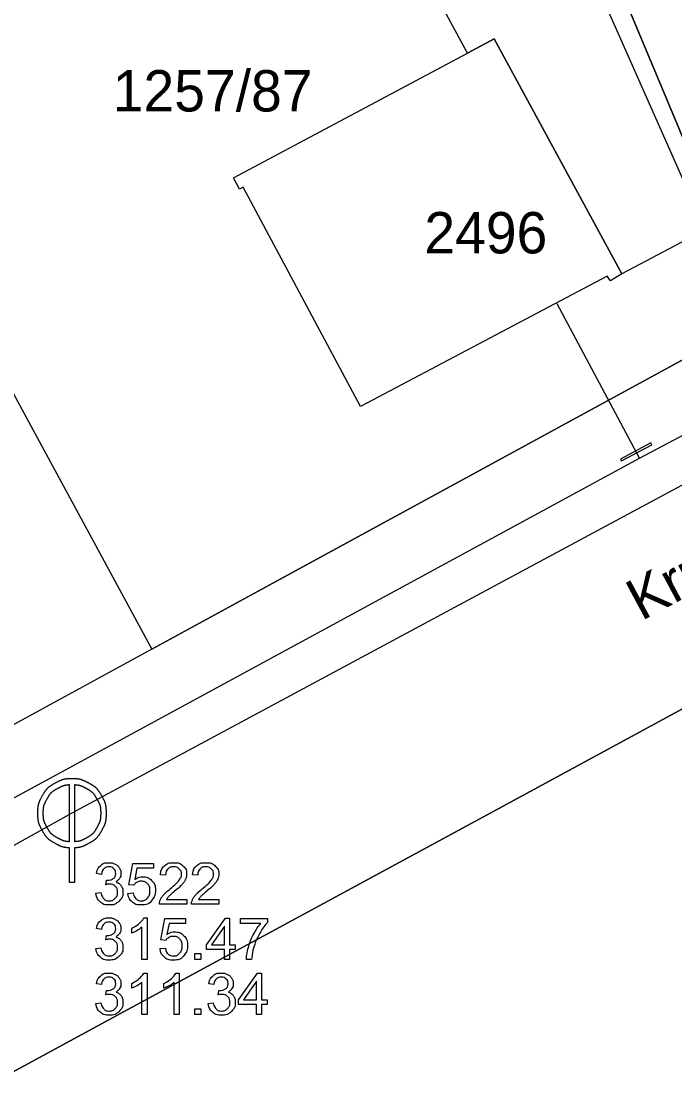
# Model space of a CAD drawing. Extents: x -562248 to -562040, y -1079385 to -1079027.
# Drawn here: x -562140.7 to -562116.99, y -1079306.51 to -1079267.68 of the extents above; entities that cross this region are included whole.
import ezdxf

# ---------------------------------------------------------------- set-up
doc = ezdxf.new("R2010")
doc.units = 0
for name, color, linetype in [('Armatura vodovodní', 7, 'Continuous'), ('Default', 7, 'Continuous'), ('Kanalizační stoka', 7, 'Continuous'), ('Kanalizační šachta', 7, 'Continuous'), ('Parcela-polygon', 7, 'Continuous'), ('Parcela-text', 7, 'Continuous'), ('Popis kmenové stoky', 7, 'Continuous'), ('Popis šachty', 7, 'Continuous'), ('Vodovodní přípojka', 7, 'Continuous'), ('Vodovodní řad', 7, 'Continuous')]:
    doc.layers.add(name, color=color, linetype=linetype)

msp = doc.modelspace()

# ---------------------------------------------------------------- linework, layer by layer
at = {"layer": 'Armatura vodovodní'}
msp.add_lwpolyline([(-562118.912, -1079283.63), (-562117.81, -1079283.04), (-562117.847, -1079282.971), (-562118.949, -1079283.561)], close=True, dxfattribs=at)
at = {"layer": 'Default'}
for points in [[(-562139.475, -1079295.321), (-562139.674, -1079295.429), (-562139.829, -1079295.582), (-562139.942, -1079295.783)], [(-562139.763, -1079295.889), (-562139.671, -1079295.722), (-562139.541, -1079295.594), (-562139.375, -1079295.504)], [(-562138.86, -1079295.16), (-562139.072, -1079295.16), (-562139.277, -1079295.214), (-562139.475, -1079295.321)], [(-562139.375, -1079295.504), (-562139.232, -1079295.428), (-562139.094, -1079295.384), (-562138.963, -1079295.372)], [(-562138.246, -1079295.321), (-562138.445, -1079295.214), (-562138.65, -1079295.16), (-562138.86, -1079295.16)], [(-562138.757, -1079295.372), (-562138.626, -1079295.384), (-562138.489, -1079295.428), (-562138.347, -1079295.504)], [(-562138.347, -1079295.504), (-562138.181, -1079295.594), (-562138.051, -1079295.722), (-562137.958, -1079295.889)], [(-562137.778, -1079295.783), (-562137.891, -1079295.582), (-562138.047, -1079295.429), (-562138.246, -1079295.321)], [(-562139.942, -1079295.783), (-562140.054, -1079295.983), (-562140.11, -1079296.192), (-562140.11, -1079296.41)], [(-562139.902, -1079296.41), (-562139.902, -1079296.229), (-562139.856, -1079296.056), (-562139.763, -1079295.889)], [(-562137.958, -1079295.889), (-562137.864, -1079296.056), (-562137.818, -1079296.229), (-562137.818, -1079296.41)], [(-562137.61, -1079296.41), (-562137.61, -1079296.192), (-562137.666, -1079295.983), (-562137.778, -1079295.783)], [(-562140.11, -1079296.41), (-562140.11, -1079296.626), (-562140.055, -1079296.834), (-562139.945, -1079297.033)], [(-562139.766, -1079296.928), (-562139.857, -1079296.763), (-562139.902, -1079296.591), (-562139.902, -1079296.41)], [(-562137.818, -1079296.41), (-562137.818, -1079296.591), (-562137.863, -1079296.763), (-562137.954, -1079296.928)], [(-562137.775, -1079297.033), (-562137.665, -1079296.834), (-562137.61, -1079296.626), (-562137.61, -1079296.41)], [(-562139.945, -1079297.033), (-562139.835, -1079297.231), (-562139.681, -1079297.385), (-562139.483, -1079297.494)], [(-562139.38, -1079297.311), (-562139.546, -1079297.22), (-562139.675, -1079297.092), (-562139.766, -1079296.928)], [(-562137.954, -1079296.928), (-562138.045, -1079297.092), (-562138.173, -1079297.22), (-562138.338, -1079297.311)], [(-562138.237, -1079297.494), (-562138.039, -1079297.385), (-562137.885, -1079297.231), (-562137.775, -1079297.033)], [(-562138.963, -1079297.445), (-562139.099, -1079297.435), (-562139.238, -1079297.391), (-562139.38, -1079297.311)], [(-562138.338, -1079297.311), (-562138.481, -1079297.391), (-562138.621, -1079297.435), (-562138.757, -1079297.445)], [(-562139.483, -1079297.494), (-562139.308, -1079297.592), (-562139.135, -1079297.646), (-562138.963, -1079297.658)], [(-562138.757, -1079297.658), (-562138.585, -1079297.646), (-562138.412, -1079297.592), (-562138.237, -1079297.494)]]:
    msp.add_open_spline(points, degree=2, dxfattribs=at)
at = {"layer": 'Kanalizační stoka'}
for points in [[(-562077.25, -1079263.3), (-562101.861, -1079276.526), (-562138.86, -1079296.41)], [(-562138.86, -1079296.41), (-562202.88, -1079332.07)]]:
    msp.add_lwpolyline(points, dxfattribs=at)
at = {"layer": 'Kanalizační šachta'}
for points in [[(-562138.963, -1079295.372), (-562138.963, -1079297.445)], [(-562138.757, -1079297.445), (-562138.757, -1079295.372)], [(-562138.963, -1079298.91), (-562138.757, -1079298.91), (-562138.757, -1079297.658)], [(-562138.963, -1079297.658), (-562138.963, -1079298.91)]]:
    msp.add_lwpolyline(points, dxfattribs=at)
at = {"layer": 'Parcela-polygon'}
for points in [[(-562125.839, -1079250.062), (-562115.46, -1079274.84), (-562111.34, -1079272.6), (-562115.82, -1079264.13), (-562111.86, -1079261.96), (-562112.48, -1079260.84), (-562109.81, -1079259.38), (-562109.2, -1079260.5), (-562101.14, -1079256.08), (-562102.73, -1079253.17), (-562100.18, -1079251.98), (-562102.28, -1079247.51), (-562108.03, -1079234.16), (-562113.76, -1079220.84), (-562114.87, -1079218.31), (-562116.77, -1079219.12), (-562123.59, -1079221.97), (-562126.807, -1079223.131)], [(-562050.734, -1079242.89), (-562074.7, -1079253.09), (-562082.29, -1079260.79), (-562083.07, -1079261.58), (-562094.62, -1079267.87), (-562113.94, -1079278.46), (-562131.57, -1079288.07), (-562135.96, -1079290.46), (-562143.99, -1079294.84), (-562166.66, -1079307.21), (-562184.27, -1079316.57), (-562201.76, -1079326), (-562209.06, -1079330.03), (-562233.192, -1079343.166)], [(-562150.955, -1079262.816), (-562144.68, -1079274.39), (-562135.96, -1079290.46), (-562131.57, -1079288.07), (-562113.94, -1079278.46), (-562115.46, -1079274.84), (-562125.839, -1079250.062)], [(-562128.35, -1079262.95), (-562129.18, -1079261.41), (-562128.95, -1079260.62), (-562129.48, -1079259.64), (-562133.24, -1079261.69), (-562134.9, -1079261.17), (-562136.63, -1079257.94), (-562126.97, -1079252.69), (-562121.01, -1079263.69), (-562121.23, -1079263.8), (-562119.71, -1079266.58), (-562115.88, -1079275.25), (-562118.9, -1079276.84), (-562119.32, -1079277.09), (-562119.43, -1079276.92), (-562128.39, -1079281.65), (-562132.65, -1079273.7), (-562132.78, -1079273.77), (-562133, -1079273.36), (-562124.5, -1079268.83), (-562127.56, -1079263.19), (-562128.35, -1079262.95)], [(-562231.237, -1079347.297), (-562217.17, -1079339.57), (-562199.49, -1079329.98), (-562196.37, -1079335.83), (-562192.03, -1079333.48), (-562171.25, -1079322.22), (-562167.46, -1079320.16), (-562158.91, -1079315.52), (-562136.96, -1079303.61), (-562123.37, -1079296.24), (-562109.61, -1079288.78), (-562108.06, -1079292.36), (-562077.04, -1079275.54), (-562045.434, -1079258.412)], [(-562098.09, -1079312.42), (-562108.06, -1079292.36), (-562109.61, -1079288.78), (-562123.37, -1079296.24), (-562136.96, -1079303.61), (-562158.91, -1079315.52), (-562167.46, -1079320.16), (-562171.25, -1079322.22), (-562162.29, -1079338.64), (-562157.03, -1079335.76), (-562146.49, -1079329.95), (-562141.95, -1079327.52), (-562136.58, -1079324.65), (-562135.92, -1079324.29), (-562132.83, -1079322.64), (-562130.32, -1079321.29), (-562116.03, -1079313.64), (-562103.22, -1079306.78), (-562099.68, -1079313.416)]]:
    msp.add_lwpolyline(points, dxfattribs=at)
for points in [[(-562129.18, -1079261.41), (-562128.95, -1079260.62), (-562129.48, -1079259.64), (-562133.24, -1079261.69), (-562134.9, -1079261.17), (-562136.63, -1079257.94), (-562126.97, -1079252.69), (-562121.01, -1079263.69), (-562121.23, -1079263.8), (-562119.71, -1079266.58), (-562115.88, -1079275.25), (-562118.9, -1079276.84), (-562123.54, -1079268.32), (-562124.5, -1079268.83), (-562127.56, -1079263.19), (-562128.35, -1079262.95)], [(-562133, -1079273.36), (-562124.5, -1079268.83), (-562123.54, -1079268.32), (-562118.9, -1079276.84), (-562119.32, -1079277.09), (-562119.43, -1079276.92), (-562128.39, -1079281.65), (-562132.65, -1079273.7), (-562132.78, -1079273.77)], [(-562144.68, -1079274.39), (-562135.96, -1079290.46), (-562143.99, -1079294.84), (-562145.99, -1079291.34), (-562153.85, -1079295.62), (-562159, -1079286.21), (-562160.69, -1079283.12), (-562153.22, -1079278.89), (-562145.79, -1079274.97)]]:
    msp.add_lwpolyline(points, close=True, dxfattribs=at)
at = {"layer": 'Popis šachty'}
for points in [[(-562136.622, -1079299.027), (-562136.795, -1079299.004), (-562136.65, -1079298.233), (-562135.904, -1079298.233), (-562135.904, -1079298.41), (-562136.503, -1079298.41), (-562136.583, -1079298.812)], [(-562137.79, -1079298.63), (-562137.974, -1079298.597)], [(-562135.463, -1079298.661), (-562135.653, -1079298.642)], [(-562134.298, -1079298.661), (-562134.488, -1079298.642)], [(-562137.629, -1079299.003), (-562137.608, -1079298.842)], [(-562137.992, -1079299.316), (-562137.808, -1079299.292)], [(-562136.828, -1079299.321), (-562136.635, -1079299.305)], [(-562134.696, -1079299.537), (-562134.696, -1079299.714), (-562135.687, -1079299.714)], [(-562135.431, -1079299.537), (-562134.696, -1079299.537)], [(-562133.531, -1079299.537), (-562133.531, -1079299.714), (-562134.522, -1079299.714)], [(-562134.266, -1079299.537), (-562133.531, -1079299.537)], [(-562136.687, -1079300.763), (-562136.687, -1079300.585)], [(-562136.135, -1079301.714), (-562136.319, -1079301.714), (-562136.319, -1079300.541)], [(-562136.254, -1079300.208), (-562136.135, -1079300.208), (-562136.135, -1079301.714)], [(-562135.457, -1079301.027), (-562135.63, -1079301.004), (-562135.485, -1079300.233), (-562134.739, -1079300.233), (-562134.739, -1079300.41), (-562135.338, -1079300.41), (-562135.418, -1079300.812)], [(-562133.326, -1079301.714), (-562133.326, -1079301.355), (-562133.977, -1079301.355), (-562133.977, -1079301.186), (-562133.293, -1079300.214), (-562133.142, -1079300.214), (-562133.142, -1079301.186), (-562132.94, -1079301.186), (-562132.94, -1079301.355), (-562133.142, -1079301.355), (-562133.142, -1079301.714), (-562133.326, -1079301.714)], [(-562133.326, -1079301.186), (-562133.326, -1079300.509), (-562133.796, -1079301.186), (-562133.326, -1079301.186)], [(-562132.739, -1079300.411), (-562132.739, -1079300.233), (-562131.768, -1079300.233), (-562131.768, -1079300.377)], [(-562132.005, -1079300.411), (-562132.739, -1079300.411)], [(-562137.79, -1079300.63), (-562137.974, -1079300.597)], [(-562137.629, -1079301.003), (-562137.608, -1079300.842)], [(-562137.992, -1079301.316), (-562137.808, -1079301.292)], [(-562135.663, -1079301.321), (-562135.47, -1079301.305)], [(-562134.395, -1079301.714), (-562134.395, -1079301.505), (-562134.186, -1079301.505), (-562134.186, -1079301.714), (-562134.395, -1079301.714)], [(-562132.34, -1079301.714), (-562132.529, -1079301.714)], [(-562136.254, -1079302.208), (-562136.135, -1079302.208), (-562136.135, -1079303.714)], [(-562135.089, -1079302.208), (-562134.97, -1079302.208), (-562134.97, -1079303.714)], [(-562132.161, -1079303.714), (-562132.161, -1079303.355), (-562132.812, -1079303.355), (-562132.812, -1079303.186), (-562132.128, -1079302.214), (-562131.977, -1079302.214), (-562131.977, -1079303.186), (-562131.775, -1079303.186), (-562131.775, -1079303.355), (-562131.977, -1079303.355), (-562131.977, -1079303.714), (-562132.161, -1079303.714)], [(-562132.161, -1079303.186), (-562132.161, -1079302.509), (-562132.631, -1079303.186), (-562132.161, -1079303.186)], [(-562137.79, -1079302.63), (-562137.974, -1079302.597)], [(-562137.629, -1079303.003), (-562137.608, -1079302.842)], [(-562136.687, -1079302.763), (-562136.687, -1079302.585)], [(-562136.135, -1079303.714), (-562136.319, -1079303.714), (-562136.319, -1079302.541)], [(-562135.522, -1079302.763), (-562135.522, -1079302.585)], [(-562134.97, -1079303.714), (-562135.154, -1079303.714), (-562135.154, -1079302.541)], [(-562133.713, -1079302.63), (-562133.897, -1079302.597)], [(-562133.552, -1079303.003), (-562133.531, -1079302.842)], [(-562137.992, -1079303.316), (-562137.808, -1079303.292)], [(-562133.915, -1079303.316), (-562133.731, -1079303.292)], [(-562134.395, -1079303.714), (-562134.395, -1079303.505), (-562134.186, -1079303.505), (-562134.186, -1079303.714), (-562134.395, -1079303.714)]]:
    msp.add_lwpolyline(points, dxfattribs=at)
for points in [[(-562137.974, -1079298.597), (-562137.94, -1079298.412), (-562137.82, -1079298.31), (-562137.7, -1079298.208), (-562137.522, -1079298.208), (-562137.399, -1079298.208), (-562137.296, -1079298.261), (-562137.193, -1079298.314), (-562137.138, -1079298.404), (-562137.083, -1079298.495), (-562137.083, -1079298.597), (-562137.083, -1079298.695), (-562137.135, -1079298.774), (-562137.187, -1079298.854), (-562137.29, -1079298.901), (-562137.157, -1079298.932), (-562137.083, -1079299.028), (-562137.01, -1079299.125), (-562137.01, -1079299.27), (-562137.01, -1079299.466), (-562137.153, -1079299.603), (-562137.296, -1079299.739), (-562137.515, -1079299.739), (-562137.713, -1079299.739), (-562137.843, -1079299.621), (-562137.974, -1079299.504), (-562137.992, -1079299.316)], [(-562135.653, -1079298.642), (-562135.633, -1079298.43), (-562135.506, -1079298.319), (-562135.38, -1079298.208), (-562135.166, -1079298.208), (-562134.95, -1079298.208), (-562134.824, -1079298.328), (-562134.698, -1079298.448), (-562134.698, -1079298.624), (-562134.698, -1079298.714), (-562134.735, -1079298.801), (-562134.772, -1079298.888), (-562134.857, -1079298.984), (-562134.942, -1079299.081), (-562135.141, -1079299.248), (-562135.306, -1079299.387), (-562135.353, -1079299.437), (-562135.4, -1079299.487), (-562135.431, -1079299.537)], [(-562134.488, -1079298.642), (-562134.468, -1079298.43), (-562134.341, -1079298.319), (-562134.215, -1079298.208), (-562134.001, -1079298.208), (-562133.785, -1079298.208), (-562133.659, -1079298.328), (-562133.533, -1079298.448), (-562133.533, -1079298.624), (-562133.533, -1079298.714), (-562133.57, -1079298.801), (-562133.607, -1079298.888), (-562133.692, -1079298.984), (-562133.777, -1079299.081), (-562133.976, -1079299.248), (-562134.141, -1079299.387), (-562134.188, -1079299.437), (-562134.235, -1079299.487), (-562134.266, -1079299.537)], [(-562137.608, -1079298.842), (-562137.59, -1079298.844), (-562137.579, -1079298.844), (-562137.461, -1079298.844), (-562137.367, -1079298.782), (-562137.273, -1079298.721), (-562137.273, -1079298.593), (-562137.273, -1079298.492), (-562137.341, -1079298.426), (-562137.41, -1079298.359), (-562137.518, -1079298.359), (-562137.626, -1079298.359), (-562137.698, -1079298.427), (-562137.769, -1079298.495), (-562137.79, -1079298.63)], [(-562135.687, -1079299.714), (-562135.689, -1079299.647), (-562135.666, -1079299.586), (-562135.628, -1079299.485), (-562135.544, -1079299.386), (-562135.461, -1079299.288), (-562135.303, -1079299.16), (-562135.059, -1079298.959), (-562134.974, -1079298.842), (-562134.888, -1079298.725), (-562134.888, -1079298.62), (-562134.888, -1079298.511), (-562134.966, -1079298.435), (-562135.044, -1079298.36), (-562135.17, -1079298.36), (-562135.303, -1079298.36), (-562135.382, -1079298.44), (-562135.462, -1079298.52), (-562135.463, -1079298.661)], [(-562134.522, -1079299.714), (-562134.524, -1079299.647), (-562134.501, -1079299.586), (-562134.463, -1079299.485), (-562134.379, -1079299.386), (-562134.296, -1079299.288), (-562134.138, -1079299.16), (-562133.894, -1079298.959), (-562133.809, -1079298.842), (-562133.723, -1079298.725), (-562133.723, -1079298.62), (-562133.723, -1079298.511), (-562133.801, -1079298.435), (-562133.879, -1079298.36), (-562134.005, -1079298.36), (-562134.138, -1079298.36), (-562134.217, -1079298.44), (-562134.297, -1079298.52), (-562134.298, -1079298.661)], [(-562137.808, -1079299.292), (-562137.776, -1079299.449), (-562137.7, -1079299.518), (-562137.624, -1079299.587), (-562137.514, -1079299.587), (-562137.384, -1079299.587), (-562137.295, -1079299.497), (-562137.205, -1079299.407), (-562137.205, -1079299.274), (-562137.205, -1079299.147), (-562137.288, -1079299.065), (-562137.371, -1079298.982), (-562137.499, -1079298.982), (-562137.551, -1079298.982), (-562137.629, -1079299.003)], [(-562136.583, -1079298.812), (-562136.448, -1079298.718), (-562136.3, -1079298.718), (-562136.104, -1079298.718), (-562135.968, -1079298.854), (-562135.833, -1079298.991), (-562135.833, -1079299.205), (-562135.833, -1079299.408), (-562135.952, -1079299.557), (-562136.096, -1079299.739), (-562136.346, -1079299.739), (-562136.551, -1079299.739), (-562136.68, -1079299.625), (-562136.81, -1079299.51), (-562136.828, -1079299.321)], [(-562136.635, -1079299.305), (-562136.613, -1079299.446), (-562136.535, -1079299.517), (-562136.457, -1079299.588), (-562136.346, -1079299.588), (-562136.212, -1079299.588), (-562136.121, -1079299.488), (-562136.029, -1079299.387), (-562136.029, -1079299.221), (-562136.029, -1079299.063), (-562136.117, -1079298.972), (-562136.205, -1079298.881), (-562136.349, -1079298.881), (-562136.439, -1079298.881), (-562136.51, -1079298.921), (-562136.581, -1079298.962), (-562136.622, -1079299.027)], [(-562137.974, -1079300.597), (-562137.94, -1079300.412), (-562137.82, -1079300.31), (-562137.7, -1079300.208), (-562137.522, -1079300.208), (-562137.399, -1079300.208), (-562137.296, -1079300.261), (-562137.193, -1079300.314), (-562137.138, -1079300.404), (-562137.083, -1079300.495), (-562137.083, -1079300.597), (-562137.083, -1079300.695), (-562137.135, -1079300.774), (-562137.187, -1079300.854), (-562137.29, -1079300.901), (-562137.157, -1079300.932), (-562137.083, -1079301.028), (-562137.01, -1079301.125), (-562137.01, -1079301.27), (-562137.01, -1079301.466), (-562137.153, -1079301.603), (-562137.296, -1079301.739), (-562137.515, -1079301.739), (-562137.713, -1079301.739), (-562137.843, -1079301.621), (-562137.974, -1079301.504), (-562137.992, -1079301.316)], [(-562137.608, -1079300.842), (-562137.59, -1079300.844), (-562137.579, -1079300.844), (-562137.461, -1079300.844), (-562137.367, -1079300.782), (-562137.273, -1079300.721), (-562137.273, -1079300.593), (-562137.273, -1079300.492), (-562137.341, -1079300.426), (-562137.41, -1079300.359), (-562137.518, -1079300.359), (-562137.626, -1079300.359), (-562137.698, -1079300.427), (-562137.769, -1079300.495), (-562137.79, -1079300.63)], [(-562136.687, -1079300.585), (-562136.533, -1079300.512), (-562136.418, -1079300.409), (-562136.302, -1079300.305), (-562136.254, -1079300.208)], [(-562136.319, -1079300.541), (-562136.386, -1079300.604), (-562136.494, -1079300.668), (-562136.602, -1079300.731), (-562136.687, -1079300.763)], [(-562132.529, -1079301.714), (-562132.526, -1079301.537), (-562132.46, -1079301.286), (-562132.393, -1079301.036), (-562132.269, -1079300.803), (-562132.145, -1079300.57), (-562132.005, -1079300.411)], [(-562131.768, -1079300.377), (-562131.911, -1079300.529), (-562132.052, -1079300.782), (-562132.192, -1079301.035), (-562132.269, -1079301.302), (-562132.324, -1079301.49), (-562132.34, -1079301.714)], [(-562137.808, -1079301.292), (-562137.776, -1079301.449), (-562137.7, -1079301.518), (-562137.624, -1079301.587), (-562137.514, -1079301.587), (-562137.384, -1079301.587), (-562137.295, -1079301.497), (-562137.205, -1079301.407), (-562137.205, -1079301.274), (-562137.205, -1079301.147), (-562137.288, -1079301.065), (-562137.371, -1079300.982), (-562137.499, -1079300.982), (-562137.551, -1079300.982), (-562137.629, -1079301.003)], [(-562135.418, -1079300.812), (-562135.283, -1079300.718), (-562135.135, -1079300.718), (-562134.938, -1079300.718), (-562134.803, -1079300.854), (-562134.668, -1079300.991), (-562134.668, -1079301.205), (-562134.668, -1079301.408), (-562134.787, -1079301.557), (-562134.931, -1079301.739), (-562135.181, -1079301.739), (-562135.386, -1079301.739), (-562135.515, -1079301.625), (-562135.645, -1079301.51), (-562135.663, -1079301.321)], [(-562135.47, -1079301.305), (-562135.448, -1079301.446), (-562135.37, -1079301.517), (-562135.292, -1079301.588), (-562135.181, -1079301.588), (-562135.047, -1079301.588), (-562134.956, -1079301.488), (-562134.864, -1079301.387), (-562134.864, -1079301.221), (-562134.864, -1079301.063), (-562134.952, -1079300.972), (-562135.04, -1079300.881), (-562135.184, -1079300.881), (-562135.274, -1079300.881), (-562135.345, -1079300.921), (-562135.416, -1079300.962), (-562135.457, -1079301.027)], [(-562137.974, -1079302.597), (-562137.94, -1079302.412), (-562137.82, -1079302.31), (-562137.7, -1079302.208), (-562137.522, -1079302.208), (-562137.399, -1079302.208), (-562137.296, -1079302.261), (-562137.193, -1079302.314), (-562137.138, -1079302.404), (-562137.083, -1079302.495), (-562137.083, -1079302.597), (-562137.083, -1079302.695), (-562137.135, -1079302.774), (-562137.187, -1079302.854), (-562137.29, -1079302.901), (-562137.157, -1079302.932), (-562137.083, -1079303.028), (-562137.01, -1079303.125), (-562137.01, -1079303.27), (-562137.01, -1079303.466), (-562137.153, -1079303.603), (-562137.296, -1079303.739), (-562137.515, -1079303.739), (-562137.713, -1079303.739), (-562137.843, -1079303.621), (-562137.974, -1079303.504), (-562137.992, -1079303.316)], [(-562137.608, -1079302.842), (-562137.59, -1079302.844), (-562137.579, -1079302.844), (-562137.461, -1079302.844), (-562137.367, -1079302.782), (-562137.273, -1079302.721), (-562137.273, -1079302.593), (-562137.273, -1079302.492), (-562137.341, -1079302.426), (-562137.41, -1079302.359), (-562137.518, -1079302.359), (-562137.626, -1079302.359), (-562137.698, -1079302.427), (-562137.769, -1079302.495), (-562137.79, -1079302.63)], [(-562136.687, -1079302.585), (-562136.533, -1079302.512), (-562136.418, -1079302.409), (-562136.302, -1079302.305), (-562136.254, -1079302.208)], [(-562135.522, -1079302.585), (-562135.368, -1079302.512), (-562135.252, -1079302.409), (-562135.137, -1079302.305), (-562135.089, -1079302.208)], [(-562133.897, -1079302.597), (-562133.863, -1079302.412), (-562133.743, -1079302.31), (-562133.623, -1079302.208), (-562133.445, -1079302.208), (-562133.322, -1079302.208), (-562133.219, -1079302.261), (-562133.116, -1079302.314), (-562133.061, -1079302.404), (-562133.006, -1079302.495), (-562133.006, -1079302.597), (-562133.006, -1079302.695), (-562133.058, -1079302.774), (-562133.11, -1079302.854), (-562133.213, -1079302.901), (-562133.08, -1079302.932), (-562133.006, -1079303.028), (-562132.933, -1079303.125), (-562132.933, -1079303.27), (-562132.933, -1079303.466), (-562133.076, -1079303.603), (-562133.219, -1079303.739), (-562133.438, -1079303.739), (-562133.636, -1079303.739), (-562133.766, -1079303.621), (-562133.897, -1079303.504), (-562133.915, -1079303.316)], [(-562133.531, -1079302.842), (-562133.513, -1079302.844), (-562133.502, -1079302.844), (-562133.384, -1079302.844), (-562133.29, -1079302.782), (-562133.196, -1079302.721), (-562133.196, -1079302.593), (-562133.196, -1079302.492), (-562133.264, -1079302.426), (-562133.333, -1079302.359), (-562133.441, -1079302.359), (-562133.549, -1079302.359), (-562133.621, -1079302.427), (-562133.692, -1079302.495), (-562133.713, -1079302.63)], [(-562136.319, -1079302.541), (-562136.386, -1079302.604), (-562136.494, -1079302.668), (-562136.602, -1079302.731), (-562136.687, -1079302.763)], [(-562135.154, -1079302.541), (-562135.221, -1079302.604), (-562135.329, -1079302.668), (-562135.437, -1079302.731), (-562135.522, -1079302.763)], [(-562137.808, -1079303.292), (-562137.776, -1079303.449), (-562137.7, -1079303.518), (-562137.624, -1079303.587), (-562137.514, -1079303.587), (-562137.384, -1079303.587), (-562137.295, -1079303.497), (-562137.205, -1079303.407), (-562137.205, -1079303.274), (-562137.205, -1079303.147), (-562137.288, -1079303.065), (-562137.371, -1079302.982), (-562137.499, -1079302.982), (-562137.551, -1079302.982), (-562137.629, -1079303.003)], [(-562133.731, -1079303.292), (-562133.699, -1079303.449), (-562133.623, -1079303.518), (-562133.547, -1079303.587), (-562133.437, -1079303.587), (-562133.307, -1079303.587), (-562133.218, -1079303.497), (-562133.128, -1079303.407), (-562133.128, -1079303.274), (-562133.128, -1079303.147), (-562133.211, -1079303.065), (-562133.294, -1079302.982), (-562133.422, -1079302.982), (-562133.474, -1079302.982), (-562133.552, -1079303.003)]]:
    msp.add_open_spline(points, degree=3, dxfattribs=at)
at = {"layer": 'Vodovodní přípojka'}
msp.add_lwpolyline([(-562118.26, -1079283.525), (-562121.254, -1079277.925)], dxfattribs=at)
at = {"layer": 'Vodovodní řad'}
msp.add_lwpolyline([(-562205.614, -1079330.519), (-562174.097, -1079314.233), (-562147.992, -1079299.695), (-562146.568, -1079298.894), (-562118.26, -1079283.525), (-562104.098, -1079276.026), (-562101.887, -1079274.855), (-562091.855, -1079269.457), (-562077.721, -1079261.793), (-562076.873, -1079261.222)], dxfattribs=at)

# ---------------------------------------------------------------- texts
at = {"layer": 'Parcela-text'}
for s, p in [('1257/87', (-562137.38, -1079270.95)), ('2496', (-562126.07, -1079276.1))]:
    msp.add_text(s, height=1.5, dxfattribs=at).set_placement(p)
at = {"layer": 'Popis kmenové stoky'}
msp.add_text('Kruhové 800 TB', height=1.5, rotation=28.2542, dxfattribs=at).set_placement((-562118.194, -1079289.45))

doc.saveas('drawing.dxf')
